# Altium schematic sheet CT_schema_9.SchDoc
size 274 x 160 mm
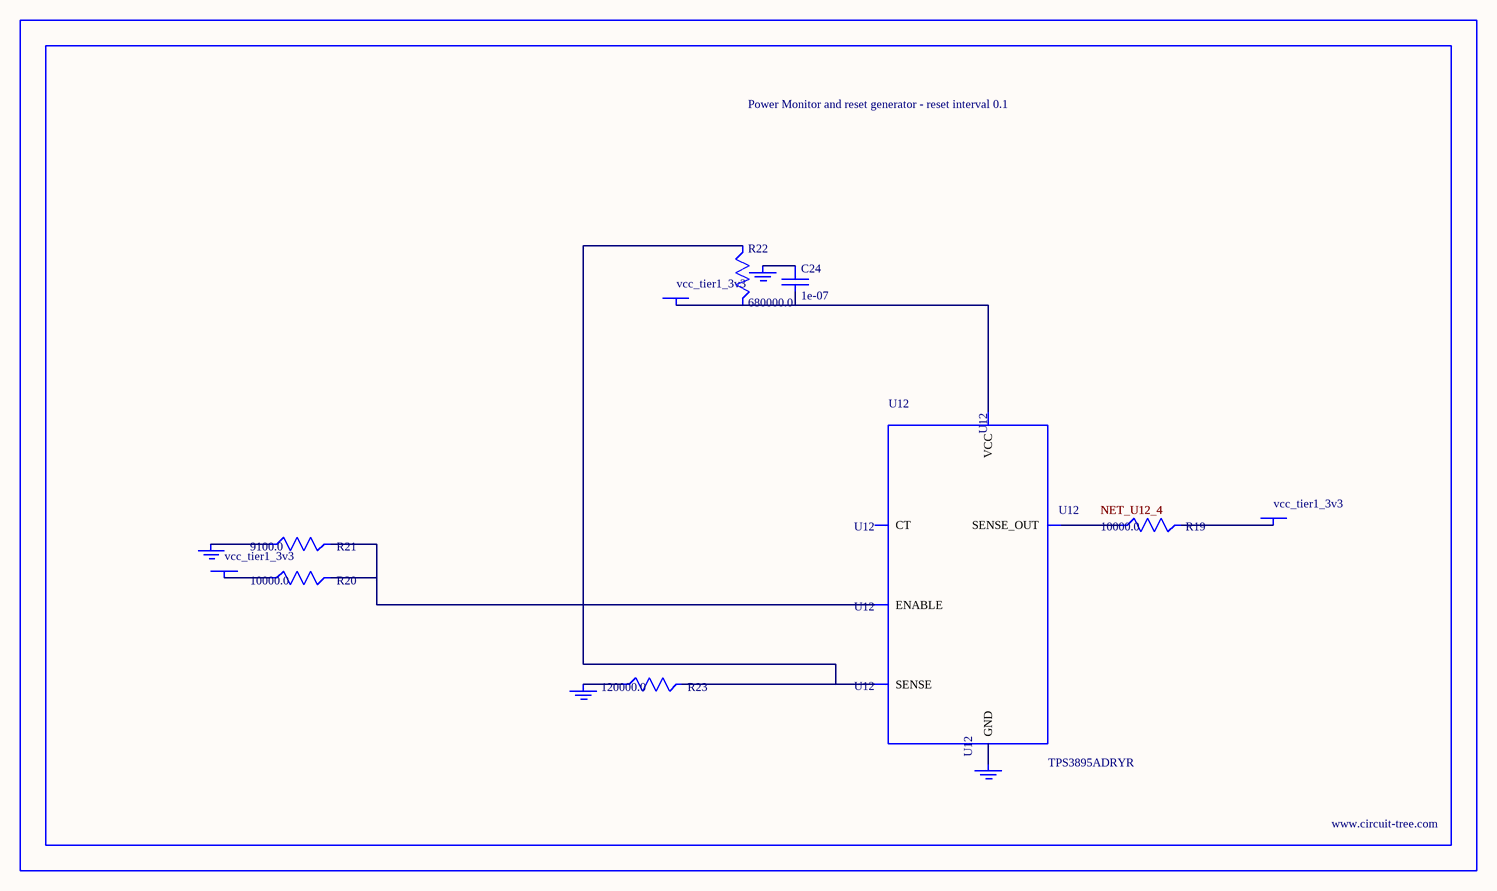
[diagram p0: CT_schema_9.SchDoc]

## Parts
BORDER8  (no value)
C24  1e-07  [C0402]
GND_INSTANCE_8_0  (no value)
GND_INSTANCE_8_1  (no value)
GND_INSTANCE_8_2  (no value)
GND_INSTANCE_8_3  (no value)
POWER_INSTANCE_8_0  vcc_tier1_3v3
POWER_INSTANCE_8_1  vcc_tier1_3v3
POWER_INSTANCE_8_2  vcc_tier1_3v3
R19  10000.0  [R0603]
R20  10000.0  [R0603]
R21  9100.0  [R0603]
R22  680000.0  [R0603]
R23  120000.0  [R0603]
U12  TPS3895ADRYR  [SON-6]

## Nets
NetC24_1: C24.1 GND_INSTANCE_8_2.0(GND)
NetC24_2: C24.2 POWER_INSTANCE_8_2.0(PWR) R22.2 U12.6(VCC)
NetGND_INSTANCE_8_0_0: GND_INSTANCE_8_0.0(GND) R21.1
NetGND_INSTANCE_8_1_0: GND_INSTANCE_8_1.0(GND) R23.1
NetGND_INSTANCE_8_3_0: GND_INSTANCE_8_3.0(GND) U12.2(GND)
NetPOWER_INSTANCE_8_0_0: POWER_INSTANCE_8_0.0(PWR) R20.1
NetPOWER_INSTANCE_8_1_0: POWER_INSTANCE_8_1.0(PWR) R19.2
NetR19_1: R19.1 U12.4(SENSE_OUT)
NetR20_2: R20.2 R21.2 U12.1(ENABLE)
NetR22_1: R22.1 R23.2 U12.3(SENSE)

Not connected (* = marked no-connect by the designer): U12 5(CT)

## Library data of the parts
BORDER8 = BORDER_PAGE8
C24 = C0402C104K3RACTU
GND_INSTANCE_8_0-GND_INSTANCE_8_3 = GND
POWER_INSTANCE_8_0-POWER_INSTANCE_8_2 = PWR
R19 R20 = RC0603JR-0710KL
R21 = RC0603JR-079K1L
R22 = RC0603JR-07680KL
R23 = RC0603JR-07120KL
